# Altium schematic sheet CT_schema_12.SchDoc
size 389 x 385 mm
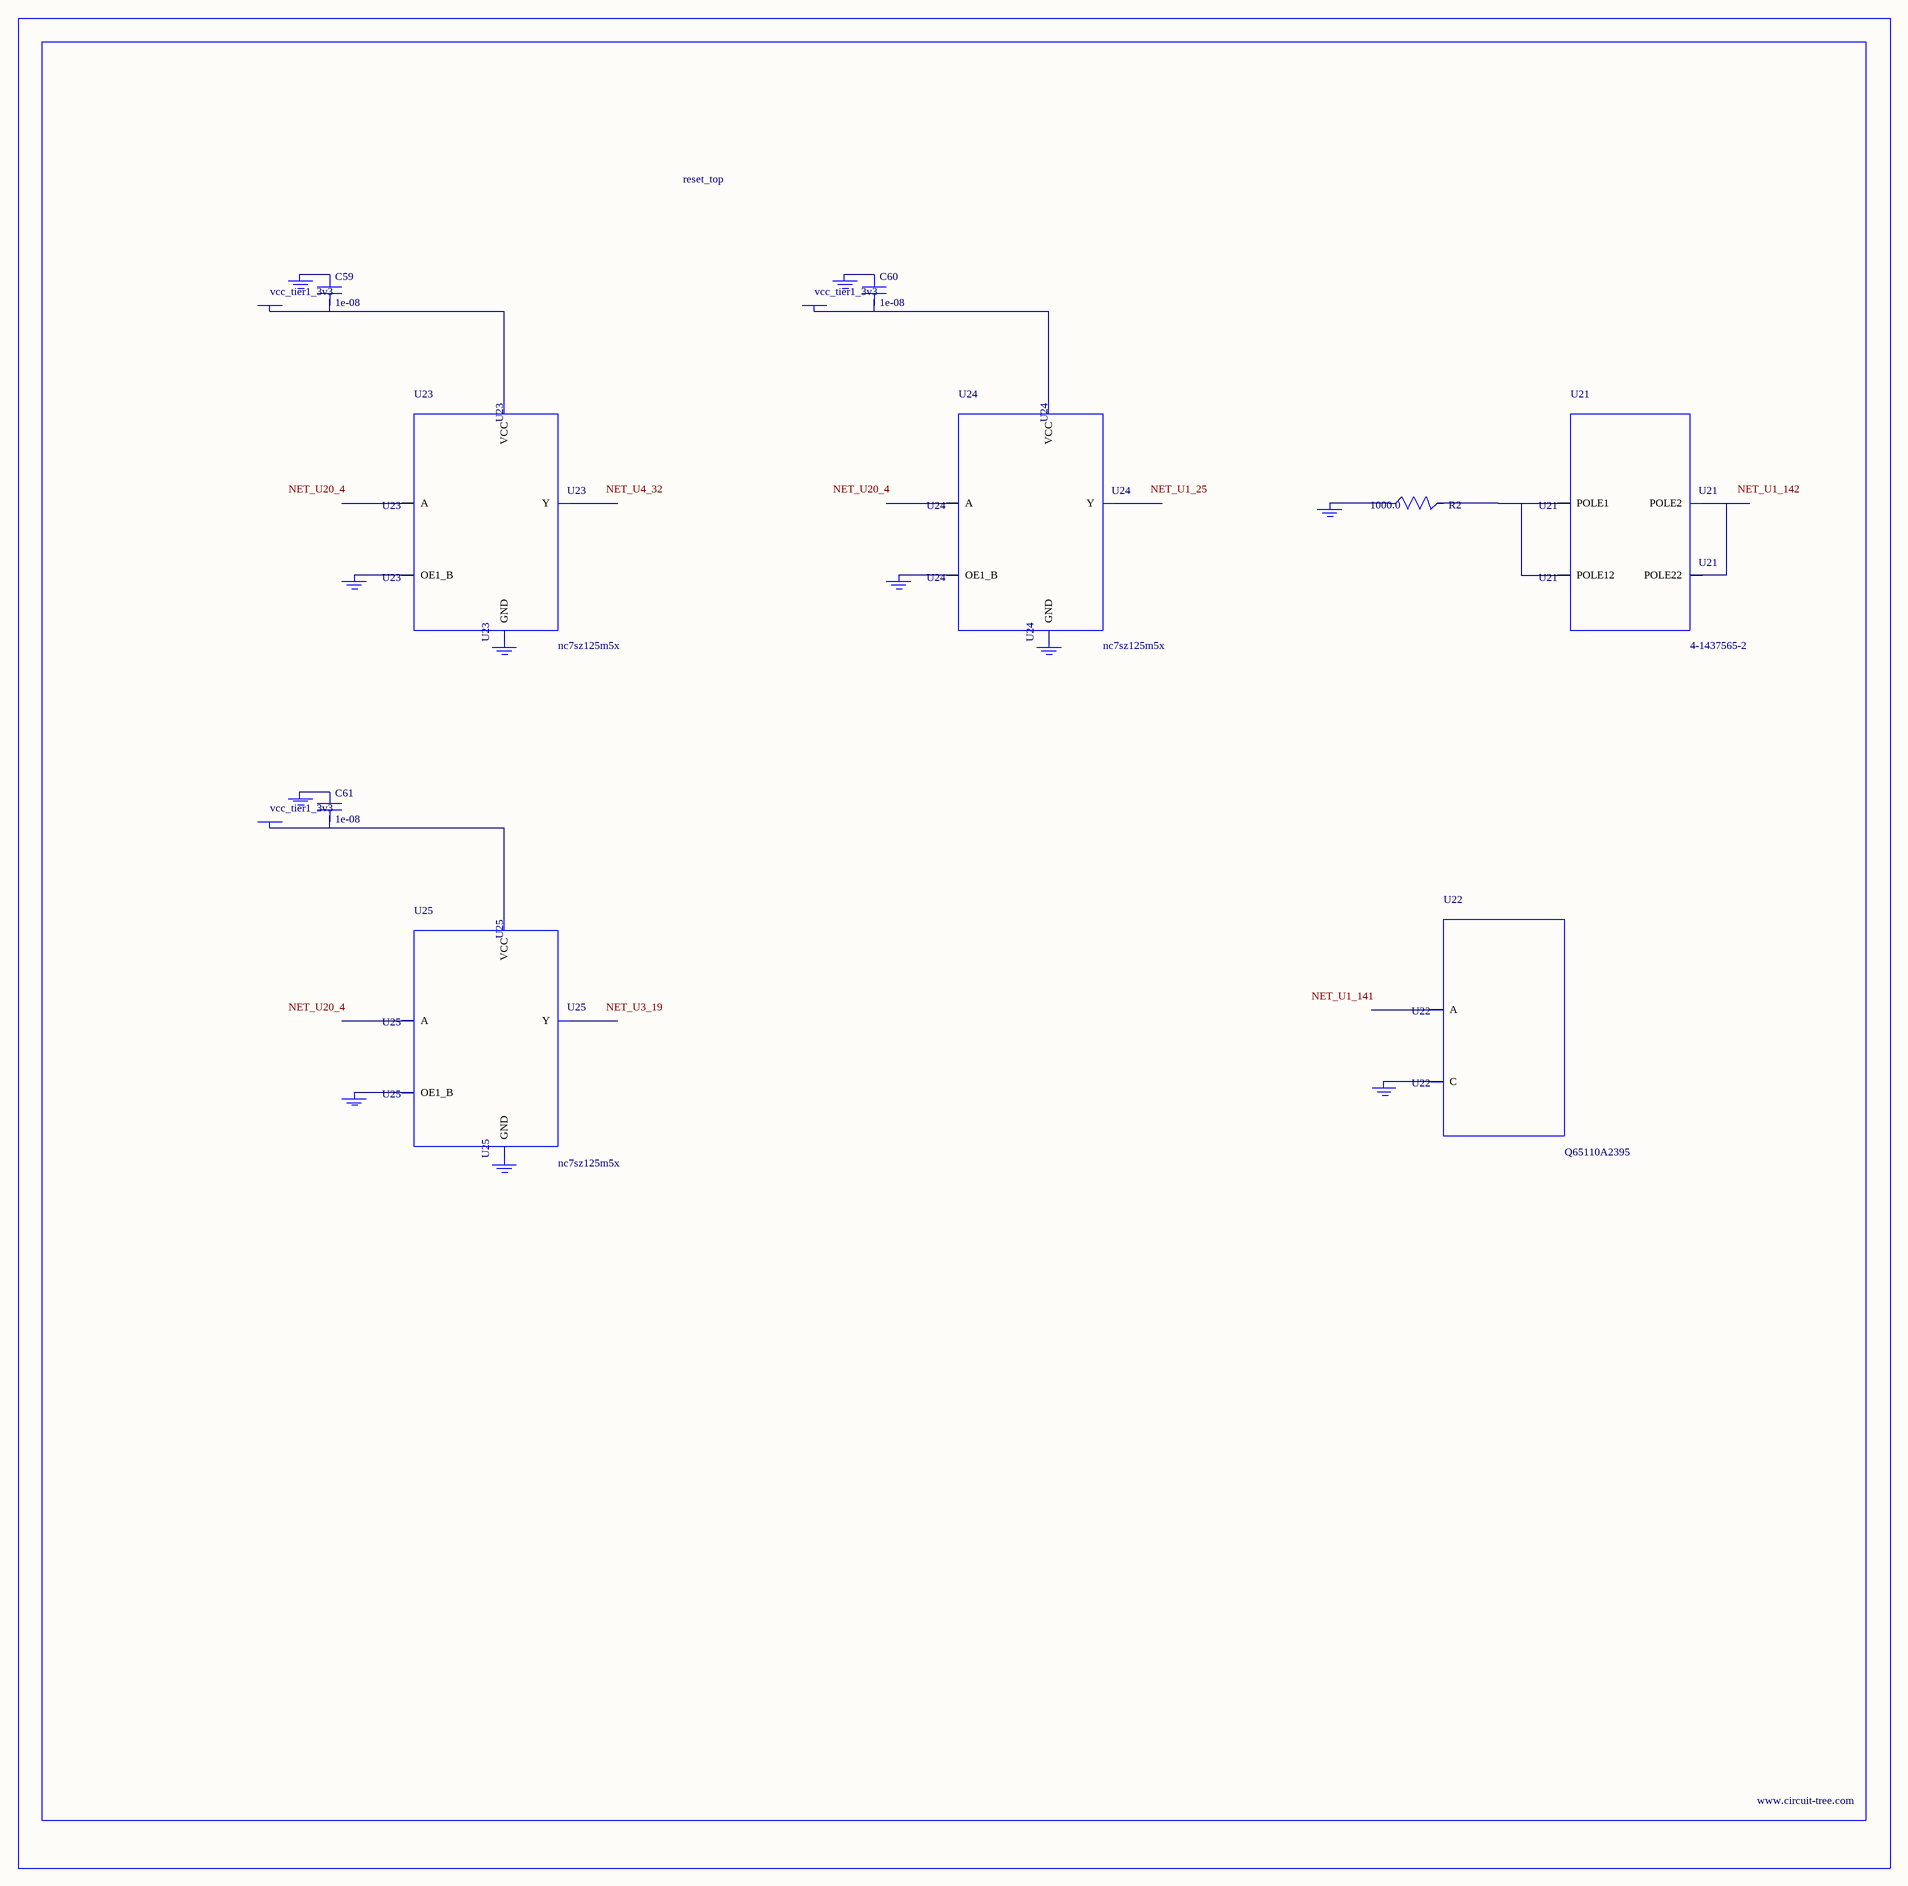
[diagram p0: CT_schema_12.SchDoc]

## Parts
BORDER11  (no value)
C59  1e-08  [C0402]
C60  1e-08  [C0402]
C61  1e-08  [C0402]
GND_INSTANCE_11_0  (no value)
GND_INSTANCE_11_1  (no value)
GND_INSTANCE_11_2  (no value)
GND_INSTANCE_11_3  (no value)
GND_INSTANCE_11_4  (no value)
GND_INSTANCE_11_5  (no value)
GND_INSTANCE_11_6  (no value)
GND_INSTANCE_11_7  (no value)
GND_INSTANCE_11_8  (no value)
GND_INSTANCE_11_9  (no value)
GND_INSTANCE_11_10  (no value)
POWER_INSTANCE_11_0  vcc_tier1_3v3
POWER_INSTANCE_11_1  vcc_tier1_3v3
POWER_INSTANCE_11_2  vcc_tier1_3v3
R2  1000.0  [R0603]
U21  4-1437565-2  [SW_4-1437565-2]
U22  Q65110A2395  [LGM67K-G1J2-24-Z]
U23  nc7sz125m5x  [NC7SZ125M5X]
U24  nc7sz125m5x  [NC7SZ125M5X]
U25  nc7sz125m5x  [NC7SZ125M5X]

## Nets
NetC59_1: C59.1 GND_INSTANCE_11_2.0(GND)
NetC59_2: C59.2 POWER_INSTANCE_11_0.0(PWR) U23.5(VCC)
NetC60_1: C60.1 GND_INSTANCE_11_5.0(GND)
NetC60_2: C60.2 POWER_INSTANCE_11_1.0(PWR) U24.5(VCC)
NetC61_1: C61.1 GND_INSTANCE_11_8.0(GND)
NetC61_2: C61.2 POWER_INSTANCE_11_2.0(PWR) U25.5(VCC)
NetGND_INSTANCE_11_0_0: GND_INSTANCE_11_0.0(GND) R2.1
NetGND_INSTANCE_11_1_0: GND_INSTANCE_11_1.0(GND) U22.C
NetGND_INSTANCE_11_3_0: GND_INSTANCE_11_3.0(GND) U23.1(OE1_B)
NetGND_INSTANCE_11_4_0: GND_INSTANCE_11_4.0(GND) U23.3(GND)
NetGND_INSTANCE_11_6_0: GND_INSTANCE_11_6.0(GND) U24.1(OE1_B)
NetGND_INSTANCE_11_7_0: GND_INSTANCE_11_7.0(GND) U24.3(GND)
NetGND_INSTANCE_11_9_0: GND_INSTANCE_11_9.0(GND) U25.1(OE1_B)
NetGND_INSTANCE_11_10_0: GND_INSTANCE_11_10.0(GND) U25.3(GND)
NetR2_2: R2.2 U21.1(POLE1) U21.2(POLE12)
NetU21_3: U21.3(POLE2) U21.4(POLE22)

Not connected (* = marked no-connect by the designer): U22 A; U23 2(A) 4(Y); U24 2(A) 4(Y); U25 2(A) 4(Y)

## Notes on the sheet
- Labels drawn without touching a wire or pin: NET_U1_25, NET_U1_141, NET_U1_142, NET_U3_19, NET_U4_32, NET_U20_4

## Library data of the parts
BORDER11 = BORDER_PAGE11
C59-C61 = C0402C103K3RAC
GND_INSTANCE_11_0-GND_INSTANCE_11_10 = GND
POWER_INSTANCE_11_0-POWER_INSTANCE_11_2 = PWR
R2 = RC0603JR-071KL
